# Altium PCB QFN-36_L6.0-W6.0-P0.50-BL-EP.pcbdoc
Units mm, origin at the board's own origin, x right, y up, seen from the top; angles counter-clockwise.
Board outline 19.36 x 19.73 mm, 2 copper layers (Top Layer, Bottom Layer), stack 0 mm thick; 1 components, 0 nets, 37 pads, 0 vias.
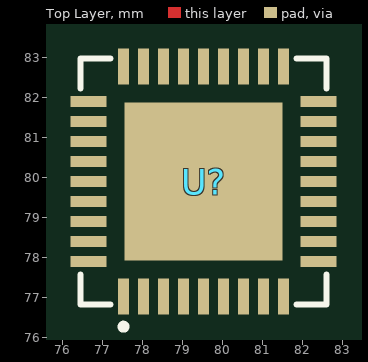
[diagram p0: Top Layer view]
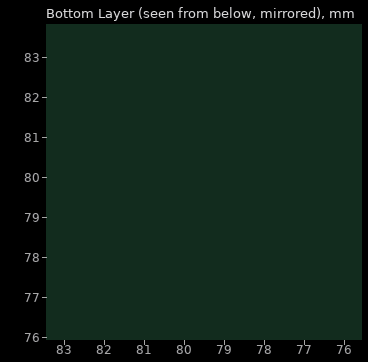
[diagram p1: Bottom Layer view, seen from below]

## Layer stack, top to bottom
Top Layer: signal copper (thickness not stored)
Bottom Layer: signal copper (thickness not stored)

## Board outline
89.21,69.85 69.85,69.85 69.85,89.585 89.21,89.585

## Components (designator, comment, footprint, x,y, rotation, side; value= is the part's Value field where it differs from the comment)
U? "" QFN-36_L6.0-W6.0-P0.50-BL-EP 79.53,79.905 r0 top

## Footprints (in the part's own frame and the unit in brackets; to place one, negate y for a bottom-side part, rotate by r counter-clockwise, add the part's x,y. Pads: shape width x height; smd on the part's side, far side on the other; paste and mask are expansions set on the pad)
QFN-36_L6.0-W6.0-P0.50-BL-EP [mm]
  rect 0.28x0.905 smd paste-100 mask+0.051: 1(-2,-2.878) 2(-1.5,-2.878) 3(-1,-2.878) 4(-0.5,-2.878) 5(0,-2.878) 6(0.5,-2.878) 7(1,-2.878) 8(1.5,-2.878) 9(2,-2.878) 19(2,2.878) 20(1.5,2.878) 21(1,2.878) 22(0.5,2.878) 23(0,2.878) 24(-0.5,2.878) 25(-1,2.878) 26(-1.5,2.878) 27(-2,2.878)
  rect 0.905x0.28 smd paste-100 mask+0.051: 10(2.878,-2) 11(2.878,-1.5) 12(2.878,-1) 13(2.878,-0.5) 14(2.878,0) 15(2.878,0.5) 16(2.878,1) 17(2.878,1.5) 18(2.878,2) 28(-2.878,2) 29(-2.878,1.5) 30(-2.878,1) 31(-2.878,0.5) 32(-2.878,0) 33(-2.878,-0.5) 34(-2.878,-1) 35(-2.878,-1.5) 36(-2.878,-2)
  rect 3.95x3.95 smd paste-100 mask+0.051: 37(0,0)
  silkscreen extent -3.08,-3.7 3.08,3.08

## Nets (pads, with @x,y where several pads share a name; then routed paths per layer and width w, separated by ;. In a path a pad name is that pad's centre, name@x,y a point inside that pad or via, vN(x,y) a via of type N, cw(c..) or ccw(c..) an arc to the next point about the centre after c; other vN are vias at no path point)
pads on no net: U?.1 U?.2 U?.3 U?.4 U?.5 U?.6 U?.7 U?.8 U?.9 U?.10 U?.11 U?.12 U?.13 U?.14 U?.15 U?.16 U?.17 U?.18 U?.19 U?.20 U?.21 U?.22 U?.23 U?.24 U?.25 U?.26 U?.27 U?.28 U?.29 U?.30 U?.31 U?.32 U?.33 U?.34 U?.35 U?.36 U?.37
